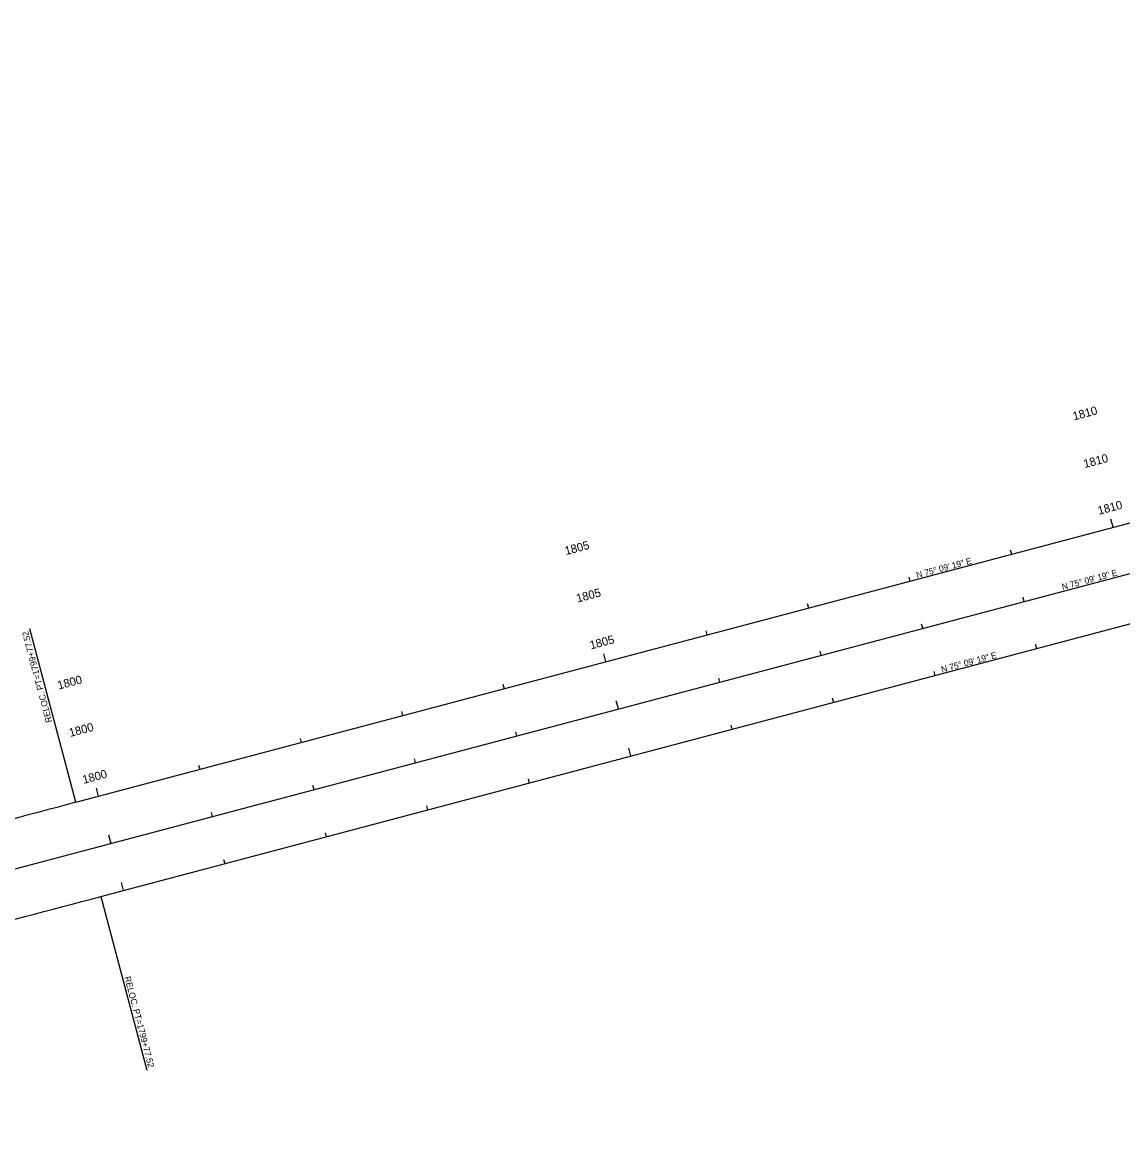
# Model space of a CAD drawing. Extents: x 2106154 to 2121963, y 864504 to 868517.
# Drawn here: x 2111041 to 2112089, y 867153 to 868210 of the extents above; entities that cross this region are included whole.
import ezdxf

# ---------------------------------------------------------------- set-up
doc = ezdxf.new("R2010")
doc.units = 0
for name, color, linetype in [('RD_HC_Cl', 7, 'Continuous'), ('RD_HC_CL_Rel', 7, 'Continuous'), ('RD_HC_Data', 7, 'Continuous'), ('RD_HC_Data_Rel', 7, 'Continuous'), ('RD_HC_Data_Tic', 7, 'Continuous'), ('RD_HC_Data_Tic_Rel', 7, 'Continuous'), ('RD_HC_TX_Rel_Sta50', 7, 'Continuous'), ('RD_HC_TX_Sta50', 7, 'Continuous')]:
    doc.layers.add(name, color=color, linetype=linetype)

msp = doc.modelspace()

# ---------------------------------------------------------------- linework, layer by layer
at = {"layer": 'RD_HC_Cl'}
msp.add_line((2110088.7, 867152.7), (2114077.7, 868210), dxfattribs=at)
at = {"layer": 'RD_HC_CL_Rel'}
for p, q in [((2111091.8, 867466.7), (2112749.4, 867906.1)), ((2111115.6, 867376.8), (2112773.2, 867816.2))]:
    msp.add_line(p, q, dxfattribs=at)
for centre, start, end in [((2116215.8, 848134.2), 104.84478, 105.70423), ((2105991.6, 886709.3), 283.98534, 284.84478)]:
    msp.add_arc(centre, 20000, start, end, dxfattribs=at)
at = {"layer": 'RD_HC_Data_Rel'}
for p, q in [((2111091.8, 867466.7), (2111047.9, 867632.1)), ((2111115.6, 867376.8), (2111159.4, 867211.4))]:
    msp.add_line(p, q, dxfattribs=at)
at = {"layer": 'RD_HC_Data_Tic'}
for p, q in [((2111995.4, 867658.1), (2111994.4, 867662)), ((2111898.7, 867632.5), (2111897.7, 867636.3)), ((2111802.1, 867606.9), (2111801.1, 867610.7)), ((2111705.4, 867581.2), (2111704.4, 867585.1)), ((2111608.8, 867555.6), (2111606.7, 867563.4)), ((2111512.1, 867530), (2111511.1, 867533.9)), ((2111415.4, 867504.4), (2111414.4, 867508.2)), ((2111318.8, 867478.8), (2111317.7, 867482.6)), ((2111222.1, 867453.1), (2111221.1, 867457)), ((2111125.4, 867427.5), (2111123.4, 867435.3))]:
    msp.add_line(p, q, dxfattribs=at)
at = {"layer": 'RD_HC_Data_Tic_Rel'}
for p, q in [((2112080.1, 867728.7), (2112078.1, 867736.4)), ((2111983.5, 867703), (2111982.4, 867706.9)), ((2111886.8, 867677.4), (2111885.8, 867681.3)), ((2111790.1, 867651.8), (2111789.1, 867655.7)), ((2111693.5, 867626.2), (2111692.5, 867630)), ((2112007.3, 867613.1), (2112006.3, 867617)), ((2111596.8, 867600.6), (2111594.8, 867608.3)), ((2111910.6, 867587.5), (2111909.6, 867591.4)), ((2111500.2, 867574.9), (2111499.1, 867578.8)), ((2111814, 867561.9), (2111812.9, 867565.8)), ((2111403.5, 867549.3), (2111402.5, 867553.2)), ((2111717.3, 867536.3), (2111716.3, 867540.2)), ((2111306.8, 867523.7), (2111305.8, 867527.6)), ((2111620.6, 867510.7), (2111618.6, 867518.4)), ((2111210.2, 867498.1), (2111209.1, 867501.9)), ((2111524, 867485), (2111523, 867488.9)), ((2111113.5, 867472.5), (2111111.5, 867480.2)), ((2111427.3, 867459.4), (2111426.3, 867463.3)), ((2111330.7, 867433.8), (2111329.6, 867437.7)), ((2111234, 867408.2), (2111233, 867412)), ((2111137.3, 867382.6), (2111135.3, 867390.3))]:
    msp.add_line(p, q, dxfattribs=at)

# ---------------------------------------------------------------- texts
at = {"layer": 'RD_HC_Data'}
msp.add_text('N 75%%d 09\' 19" E', height=6, rotation=14.8448, dxfattribs=at).set_placement((2112032.1, 867668.9))
at = {"layer": 'RD_HC_Data_Rel'}
for s, rotation, p in [('N 75%%d 09\' 19" E', 14.8448, (2111893.4, 867680.2)), ('RELOC. PT=1799+77.52', 104.8448, (2111069.3, 867543.5)), ('N 75%%d 09\' 19" E', 14.8448, (2111917.2, 867590.3)), ('RELOC. PT=1799+77.52', 284.8448, (2111138, 867300))]:
    msp.add_text(s, height=6, rotation=rotation, dxfattribs=at).set_placement(p)
at = {"layer": 'RD_HC_TX_Rel_Sta50'}
for s, p in [('1810', (2112042.8, 867830.5)), ('1810', (2112066.6, 867740.6)), ('1805', (2111558.8, 867702.2)), ('1805', (2111582.6, 867612.3)), ('1800', (2111075.5, 867574.1)), ('1800', (2111099.3, 867484.2))]:
    msp.add_text(s, height=8, rotation=14.8448, dxfattribs=at).set_placement(p)
at = {"layer": 'RD_HC_TX_Sta50'}
for s, p in [('1810', (2112053.1, 867785.1)), ('1805', (2111569.8, 867657)), ('1800', (2111086.5, 867528.9))]:
    msp.add_text(s, height=8, rotation=14.8448, dxfattribs=at).set_placement(p)

doc.saveas('drawing.dxf')
